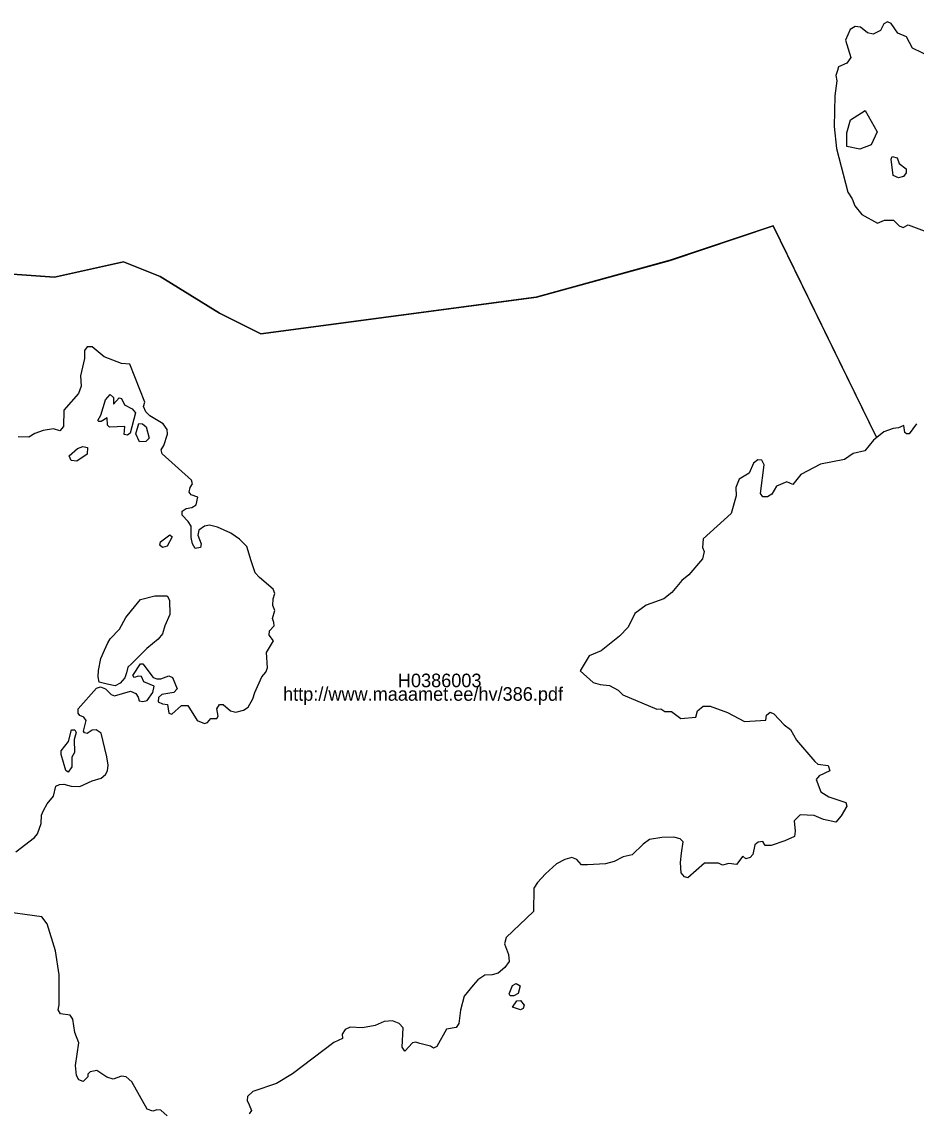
# Model space of a CAD drawing. Extents: x 369010 to 739155, y 6377141 to 6634081.
# Drawn here: x 447552 to 449202, y 6475229 to 6477243 of the extents above; entities that cross this region are included whole.
import ezdxf

# ---------------------------------------------------------------- set-up
doc = ezdxf.new("R2010")
doc.units = 0
for name, color, linetype in [('H_LINK', 7, 'Continuous'), ('H_PIIR', 7, 'Continuous'), ('H_TUNNUS', 7, 'Continuous')]:
    doc.layers.add(name, color=color, linetype=linetype)

msp = doc.modelspace()

# ---------------------------------------------------------------- linework, layer by layer
at = {"layer": 'H_PIIR'}
for points in [[(449248.9837, 6477167.9922), (449195.7438, 6477194.0521), (449184.2538, 6477215.1222), (449168.5438, 6477222.0121), (449155.9038, 6477239.6421), (449149.3938, 6477242.7021), (449142.4938, 6477239.2521), (449136.7538, 6477226.6121), (449122.9638, 6477219.7121), (449112.6238, 6477222.4021), (449099.5937, 6477233.1222), (449089.6338, 6477234.2722), (449080.2538, 6477228.5322), (449072.2138, 6477208.6121), (449081.7839, 6477176.8121), (449074.5138, 6477166.4621), (449058.8038, 6477159.9522), (449057.2738, 6477152.6721), (449054.2038, 6477143.8621), (449055.9338, 6477133.9122), (449051.9615, 6477105.9225), (449051.3, 6477049.6985), (449055.2688, 6477008.688), (449076.4355, 6476928.6513), (449084.373, 6476916.0836), (449089.4538, 6476902.8921), (449102.0938, 6476887.1821), (449131.0138, 6476871.0921), (449144.0437, 6476876.4522), (449160.5138, 6476876.8421), (449170.8538, 6476866.1122), (449178.1339, 6476863.4321), (449187.7038, 6476868.0321), (449216.8239, 6476856.9222)], [(449203.2238, 6476500.6421), (449189.6237, 6476482.2521), (449184.2638, 6476482.2521), (449181.1938, 6476484.9421), (449179.6638, 6476497.5822), (449169.7038, 6476493.3622), (449160.1237, 6476492.2222), (449142.8937, 6476486.0921), (449129.5129, 6476475.8543), (449129.3938, 6476476.0975), (448938.2538, 6476866.4275), (448748.3339, 6476802.6475), (448501.4838, 6476734.9674), (447993.3238, 6476666.8674), (447916.8037, 6476705.0576), (447807.5338, 6476772.7375), (447739.8938, 6476800.0675), (447612.4138, 6476771.4276), (447508.3439, 6476779.2375)], [(447508.3968, 6476779.1449), (447612.4667, 6476771.335), (447739.9467, 6476799.9749), (447807.5867, 6476772.6449), (447916.8566, 6476704.965), (447993.3767, 6476666.7748), (448501.5367, 6476734.8748), (448748.3868, 6476802.5549), (448938.3067, 6476866.3349), (449129.4467, 6476476.0049), (449129.5658, 6476475.7617), (449123.4068, 6476471.0495), (449107.7066, 6476451.1296), (449086.2567, 6476446.1495), (449069.9767, 6476435.4295), (449025.9268, 6476426.2295), (448989.5368, 6476407.4596), (448974.9766, 6476389.0695), (448963.6867, 6476394.0496), (448944.9167, 6476386.0096), (448935.7166, 6476371.0696), (448928.0567, 6476366.4696), (448919.2467, 6476366.0895), (448915.4167, 6476372.5995), (448921.9266, 6476425.0895), (448917.7167, 6476433.8996), (448910.4368, 6476434.2795), (448902.3968, 6476428.1496), (448894.3468, 6476410.1396), (448875.9667, 6476399.0295), (448869.8367, 6476383.3295), (448870.2167, 6476367.9996), (448860.8368, 6476335.4395), (448809.5068, 6476288.6995), (448808.3568, 6476272.9896), (448811.0367, 6476265.3296), (448807.9767, 6476251.9195), (448782.6967, 6476222.4195), (448769.6668, 6476211.6896), (448751.7968, 6476189.9096), (448736.8668, 6476177.7996), (448704.2967, 6476166.4895), (448683.0366, 6476150.8795), (448671.1547, 6476125.8402), (448655.0151, 6476108.9068), (448621.3968, 6476081.9596), (448599.1033, 6476072.8718), (448582.2783, 6476045.2802), (448606.4568, 6476023.5295), (448619.1068, 6476019.7695), (448636.3366, 6476017.8796), (448652.2167, 6476009.8096), (448660.8267, 6476000.9195), (448723.8167, 6475974.5396), (448731.3567, 6475975.3495), (448738.8867, 6475970.2395), (448751.0866, 6475969.9596), (448767.9468, 6475957.3096), (448795.7068, 6475959.6096), (448799.1568, 6475971.1096), (448809.4968, 6475980.2996), (448822.1366, 6475980.2996), (448854.3167, 6475968.4195), (448885.3467, 6475951.9495), (448924.9867, 6475954.2495), (448926.1367, 6475963.4495), (448933.0268, 6475969.1895), (448939.9268, 6475965.7495), (448959.03, 6475945.57), (448970.5551, 6475936.8008), (448981.2966, 6475917.4796), (449015.1967, 6475877.6396), (449020.9467, 6475873.0396), (449040.0967, 6475870.7396), (449043.1568, 6475860.7795), (449023.6268, 6475851.5895), (449017.8767, 6475844.6896), (449026.3066, 6475822.0895), (449041.2467, 6475812.8995), (449072.6568, 6475802.5495), (449074.1866, 6475795.2796), (449064.2267, 6475777.6495), (449053.8867, 6475766.1595), (449031.2867, 6475771.1395), (449014.0467, 6475778.4196), (448988.4168, 6475779.4796), (448977.5267, 6475768.1396), (448979.3467, 6475749.5396), (448977.9868, 6475739.5595), (448959.8367, 6475731.3895), (448934.8867, 6475722.7695), (448923.9967, 6475722.7695), (448919.4667, 6475730.0296), (448910.8467, 6475729.1195), (448904.9467, 6475724.1296), (448900.8667, 6475706.4296), (448895.8767, 6475700.5396), (448888.1567, 6475698.2696), (448882.2668, 6475703.2595), (448870.6747, 6475688.092), (448856.887, 6475689.7193), (448845.27, 6475686.7), (448837.3125, 6475690.4487), (448811.9125, 6475690.4487), (448781.1846, 6475662.9908), (448774.8346, 6475665.2607), (448768.4847, 6475672.5207), (448767.69, 6475691.65), (448769.4714, 6475708.5973), (448772.5968, 6475729.5595), (448766.7069, 6475735.4594), (448754.907, 6475738.1795), (448733.2925, 6475737.7552), (448710.4124, 6475733.7152), (448698.8026, 6475725.1916), (448678.6226, 6475705.8117), (448661.554, 6475701.7573), (448644.864, 6475693.1373), (448629.244, 6475689.3672), (448596.0868, 6475687.2996), (448585.0568, 6475687.0295), (448576.1667, 6475697.2595), (448567.2867, 6475700.7595), (448553.9668, 6475696.9896), (448538.8968, 6475689.1795), (448518.4367, 6475670.8695), (448503.6366, 6475654.4496), (448496.9067, 6475644.2195), (448496.4967, 6475601.1395), (448445.8866, 6475553.2195), (448442.9267, 6475541.3796), (448449.9266, 6475521.9995), (448451.1466, 6475508.7995), (448443.3367, 6475498.0296), (448430.9566, 6475487.5296), (448420.1867, 6475484.5695), (448406.7268, 6475483.4996), (448393.8067, 6475475.1495), (448384.9267, 6475465.1896), (448368.3667, 6475445.0596), (448361.7368, 6475418.8495), (448358.4967, 6475394.4095), (448353.7867, 6475387.3396), (448335.5267, 6475383.7996), (448318.1567, 6475352.2895), (448311.6767, 6475349.0496), (448306.3768, 6475352.8795), (448286.5167, 6475357.8796), (448279.4467, 6475359.9395), (448272.9668, 6475358.7695), (448259.1268, 6475343.4496), (448254.1267, 6475351.1095), (448255.5968, 6475386.4495), (448248.5266, 6475394.6996), (448235.8666, 6475399.6995), (448220.8466, 6475397.9395), (448203.9167, 6475390.5695), (448180.9467, 6475386.7396), (448158.2667, 6475387.6295), (448148.5567, 6475383.2096), (448143.2567, 6475374.9595), (448144.1366, 6475367.0096), (448127.7967, 6475359.3495), (448051.5267, 6475301.6295), (448021.9268, 6475283.6595), (447978.3467, 6475269.2195), (447968.6267, 6475259.7996), (447967.7468, 6475252.4395), (447971.8667, 6475244.4895), (447975.6966, 6475233.8796), (447971.8667, 6475227.6995)], [(447540.9367, 6475711.5296), (447575.7866, 6475737.9095), (447581.1768, 6475744.6395), (447587.9066, 6475763.7595), (447588.4466, 6475779.0996), (447592.0768, 6475787.7096), (447599.0767, 6475800.0995), (447610.3766, 6475813.8295), (447614.6867, 6475832.6696), (447621.4166, 6475835.6296), (447629.7567, 6475836.1696), (447643.4868, 6475832.3995), (447659.3667, 6475831.5896), (447681.8367, 6475842.3595), (447698.7968, 6475847.2096), (447706.6067, 6475853.9396), (447710.1067, 6475860.9396), (447711.7167, 6475871.1695), (447709.0267, 6475886.2396), (447698.3867, 6475930.1196), (447689.2367, 6475936.0496), (447681.7067, 6475935.5096), (447672.5467, 6475929.8595), (447667.9767, 6475930.6596), (447665.8166, 6475933.8895), (447670.9367, 6475953.5495), (447666.6267, 6475959.4695), (447659.0967, 6475962.9696), (447656.1268, 6475967.2795), (447656.1268, 6475974.8095), (447689.7767, 6476013.3096), (447697.3167, 6476015.4595), (447706.4667, 6476012.2296), (447716.9667, 6476001.4695), (447723.1567, 6475998.7696), (447752.4968, 6476007.3896), (447762.7266, 6476003.3496), (447766.7566, 6475996.3495), (447768.9167, 6475989.6196), (447775.3767, 6475988.8095), (447783.5766, 6475990.4195), (447793.8067, 6476005.2296), (447796.4967, 6476016.8096), (447777.3867, 6476024.8796), (447772.8167, 6476034.8395), (447767.1567, 6476035.6495), (447760.1667, 6476032.6895), (447757.1967, 6476036.7295), (447771.1967, 6476058.2696), (447775.5066, 6476058.2696), (447794.6168, 6476032.6895), (447801.0767, 6476030.2695), (447808.8866, 6476030.5396), (447823.1467, 6476035.9195), (447830.1467, 6476032.9596), (447838.7567, 6476011.9595), (447832.5666, 6476005.2296), (447810.7668, 6476001.4595), (447804.3066, 6475995.8095), (447804.0367, 6475988.2695), (447811.8466, 6475984.2295), (447820.9966, 6475982.8895), (447823.6867, 6475967.2695), (447829.0666, 6475965.3896), (447846.5668, 6475981.5396), (447858.5466, 6475980.9996), (447875.7767, 6475953.2696), (447889.2368, 6475947.8895), (447894.8866, 6475949.7696), (447901.0767, 6475957.3096), (447912.1067, 6475957.0395), (447914.2667, 6475961.3496), (447912.1067, 6475975.3495), (447917.2267, 6475983.1495), (447923.8168, 6475982.8795), (447937.0066, 6475971.5695), (447946.9668, 6475968.8796), (447960.9667, 6475972.3796), (447969.8466, 6475978.0296), (447978.1867, 6475993.6496), (447981.9566, 6476005.2196), (447995.1467, 6476034.2995), (448002.5567, 6476042.9195), (448005.5167, 6476050.9895), (448003.3566, 6476079.2595), (448016.2767, 6476100.5296), (448008.7467, 6476110.7596), (448009.0167, 6476118.8296), (448017.6267, 6476127.9896), (448017.3568, 6476134.4496), (448014.5267, 6476141.9896), (448018.8367, 6476156.2596), (448015.0668, 6476165.6796), (448015.8767, 6476178.0695), (448019.1068, 6476187.7595), (448016.1468, 6476195.8295), (447990.5667, 6476217.3695), (447983.0367, 6476225.7196), (447975.3667, 6476248.3295), (447967.5566, 6476274.7196), (447953.8268, 6476287.9096), (447937.9467, 6476298.9496), (447913.0467, 6476310.2495), (447898.2467, 6476313.7495), (447889.3667, 6476312.1396), (447878.5967, 6476304.5996), (447876.7167, 6476295.7195), (447883.1767, 6476279.5595), (447881.8267, 6476272.8296), (447871.8668, 6476271.2196), (447867.0167, 6476279.2996), (447864.5967, 6476291.4096), (447864.4568, 6476311.8695), (447859.3467, 6476320.4795), (447848.3068, 6476332.3296), (447847.7767, 6476339.8696), (447855.5767, 6476344.9796), (447865.6767, 6476346.3296), (447874.0167, 6476351.4496), (447877.2467, 6476365.4495), (447864.5967, 6476370.0195), (447860.8366, 6476374.8695), (447862.7168, 6476383.2196), (447867.2968, 6476389.9496), (447865.4066, 6476397.2095), (447811.0367, 6476445.3996), (447809.4167, 6476452.6695), (447814.3967, 6476461.0196), (447821.1268, 6476482.0195), (447820.3267, 6476490.6295), (447812.7867, 6476500.8596), (447788.2868, 6476515.6695), (447781.2968, 6476522.9395), (447776.9867, 6476532.8995), (447779.1367, 6476540.9795), (447751.4167, 6476611.2395), (447736.3468, 6476612.3195), (447703.9166, 6476624.6995), (447682.1068, 6476643.2796), (447672.6866, 6476643.2796), (447667.8467, 6476636.2795), (447667.8467, 6476621.4696), (447660.3067, 6476589.4395), (447661.3868, 6476570.5896), (447656.9467, 6476557.1295), (447629.4966, 6476526.1696), (447628.9568, 6476496.2896), (447622.2267, 6476488.2096), (447610.7867, 6476491.4395), (447591.6767, 6476488.7496), (447576.0567, 6476483.0895), (447565.2967, 6476476.6296), (447545.3768, 6476476.8995)], [(447820.4766, 6475224.1695), (447808.8367, 6475234.4796), (447801.4768, 6475235.3595), (447793.8267, 6475233.0095), (447783.5166, 6475236.2495), (447755.2466, 6475286.6095), (447744.6467, 6475296.0296), (447736.4067, 6475297.4995), (447720.6466, 6475291.9095), (447709.1568, 6475295.4496), (447690.3167, 6475307.8195), (447678.5366, 6475305.4595), (447674.1167, 6475301.0395), (447673.8267, 6475296.0396), (447665.5767, 6475287.1995), (447657.6267, 6475290.7295), (447652.9167, 6475298.6895), (447651.4466, 6475316.9496), (447657.6267, 6475358.7695), (447650.2666, 6475377.6195), (447646.1466, 6475402.3596), (447641.1368, 6475409.7196), (447623.3167, 6475412.0696), (447619.4967, 6475419.7295), (447621.2567, 6475428.8596), (447621.2567, 6475484.2296), (447614.1567, 6475528.4595), (447598.9466, 6475578.2696), (447589.2568, 6475591.1895), (447508.0967, 6475602.2295)]]:
    msp.add_lwpolyline(points, dxfattribs=at)
for points in [[(449098.4136, 6477007.6982), (449074.601, 6477012.4607), (449074.601, 6477037.8608), (449080.951, 6477061.6733), (449107.9386, 6477079.1358), (449130.1636, 6477039.4483), (449119.0511, 6477015.6357)], [(449169.5513, 6476954.5604), (449159.9521, 6476959.1946), (449156.1454, 6476989.1508), (449157.9659, 6476994.1158), (449167.5653, 6476991.4678), (449170.7099, 6476981.0411), (449183.6191, 6476971.4419), (449184.1157, 6476964.1596), (449179.1505, 6476957.2084)], [(447715.1021, 6476554.8683), (447721.0603, 6476549.7376), (447721.5569, 6476536.9938), (447731.6525, 6476548.9101), (447735.9557, 6476547.7516), (447741.7483, 6476536.1663), (447755.4852, 6476528.3876), (447761.7744, 6476520.94), (447751.844, 6476483.7016), (447746.879, 6476479.895), (447741.0862, 6476481.55), (447742.4103, 6476495.7834), (447713.7782, 6476494.9559), (447709.9716, 6476498.7625), (447709.475, 6476512.0028), (447698.5517, 6476505.0516), (447694.2487, 6476505.548), (447692.2625, 6476507.3687), (447697.7242, 6476516.8024), (447706.3304, 6476545.1036)], [(447781.3037, 6476468.1442), (447769.3874, 6476467.8131), (447762.4362, 6476482.7085), (447768.3944, 6476501.576), (447774.8491, 6476501.245), (447781.8003, 6476495.2868), (447786.931, 6476474.5988)], [(447664.9545, 6476458.876), (447673.2296, 6476457.3864), (447673.0641, 6476444.9736), (447653.7003, 6476432.2298), (447642.9424, 6476433.3884), (447639.6324, 6476441.9946), (447654.6932, 6476455.4004)], [(447825.1623, 6476296.02), (447829.4655, 6476292.379), (447820.1972, 6476275.332), (447811.591, 6476272.8495), (447807.1224, 6476276.987), (447807.9499, 6476283.4417)], [(447733.6255, 6476022.3937), (447724.3651, 6476017.7635), (447709.813, 6476020.4093), (447694.5994, 6476024.3781), (447693.2765, 6476034.3), (447693.938, 6476045.5448), (447697.9067, 6476068.0344), (447704.5213, 6476083.248), (447711.1359, 6476097.1387), (447715.1047, 6476104.4147), (447732.3026, 6476122.2741), (447744.2089, 6476143.4408), (447754.7923, 6476156.67), (447771.3287, 6476176.5138), (447797.7871, 6476183.7899), (447820.2768, 6476183.7899), (447824.907, 6476175.8524), (447825.5684, 6476149.394), (447816.308, 6476128.2273), (447811.6778, 6476113.6752), (447803.7403, 6476103.7533), (447782.5736, 6476086.5553), (447754.7923, 6476058.1125), (447747.5162, 6476052.1594), (447745.5318, 6476041.5761), (447742.2245, 6476032.3156)], [(447643.77, 6475936.3799), (447650.2246, 6475936.2144), (447652.3762, 6475931.5803), (447648.735, 6475918.671), (447649.5625, 6475894.3419), (447644.7629, 6475885.7357), (447644.7629, 6475868.3578), (447637.8117, 6475858.262), (447633.5087, 6475861.572), (447624.5716, 6475890.8662), (447625.068, 6475897.3208), (447638.3083, 6475914.8644)], [(448464.5042, 6475468.1691), (448471.7865, 6475464.0315), (448467.9799, 6475450.1291), (448460.0357, 6475445.495), (448453.25, 6475445.495), (448451.264, 6475449.3016), (448457.3875, 6475464.859)], [(448472.4485, 6475437.2199), (448478.9032, 6475428.2825), (448477.4136, 6475422.159), (448472.4485, 6475419.842), (448457.7186, 6475424.4759), (448465.3317, 6475436.0613)]]:
    msp.add_lwpolyline(points, close=True, dxfattribs=at)

# ---------------------------------------------------------------- texts
at = {"layer": 'H_LINK'}
msp.add_text('http://www.maaamet.ee/hv/386.pdf', height=25, rotation=0, dxfattribs=at).set_placement((448034.2181, 6475990.0072))
at = {"layer": 'H_TUNNUS'}
msp.add_text('H0386003', height=25, rotation=0, dxfattribs=at).set_placement((448246.0726, 6476015.0072))

doc.saveas('drawing.dxf')
